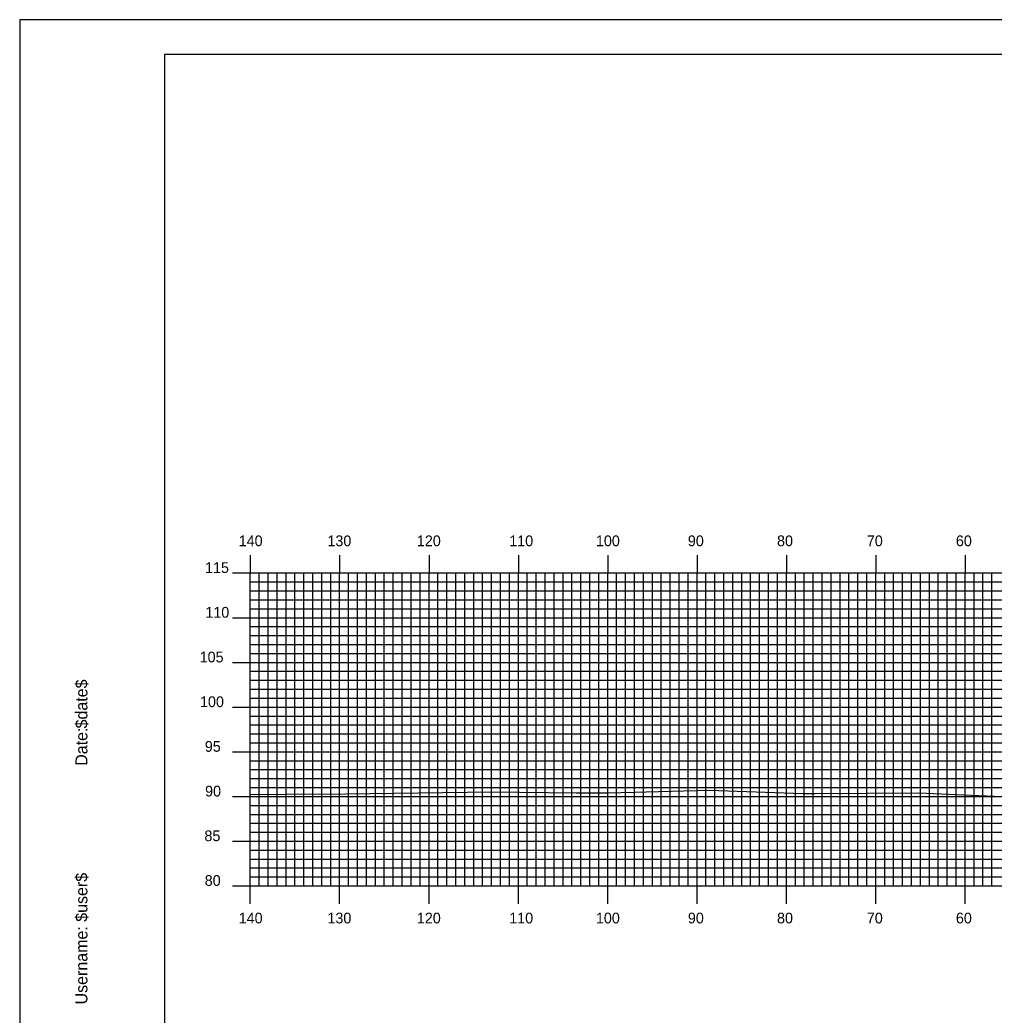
# Model space of a CAD drawing. Extents: x 1761397 to 1761741, y 442591 to 442811.
# Drawn here: x 1761397.5 to 1761506.5, y 442699.2 to 442810.5 of the extents above; entities that cross this region are included whole.
import ezdxf

# ---------------------------------------------------------------- set-up
doc = ezdxf.new("R2010")
doc.units = 0
for name, color, linetype in [('BORDER', 7, 'Continuous'), ('H_V ANNOTATION', 7, 'Continuous'), ('MAJOR', 7, 'Continuous'), ('MINOR', 7, 'Continuous'), ('PLOT BOUNDARY', 7, 'Continuous'), ('S_Roadway_Centerline', 7, 'Continuous')]:
    doc.layers.add(name, color=color, linetype=linetype)

msp = doc.modelspace()

# ---------------------------------------------------------------- linework, layer by layer
at = {"layer": 'BORDER'}
msp.add_lwpolyline([(1761413.64, 442596.67), (1761733.64, 442596.67), (1761733.64, 442806.67), (1761413.64, 442806.67)], close=True, dxfattribs=at)
at = {"layer": 'MAJOR'}
for p, q in [((1761423.24, 442750.67), (1761423.24, 442748.67)), ((1761433.24, 442750.67), (1761433.24, 442748.67)), ((1761443.24, 442750.67), (1761443.24, 442748.67)), ((1761453.24, 442750.67), (1761453.24, 442748.67)), ((1761463.24, 442750.67), (1761463.24, 442748.67)), ((1761473.24, 442750.67), (1761473.24, 442748.67)), ((1761483.24, 442750.67), (1761483.24, 442748.67)), ((1761493.24, 442750.67), (1761493.24, 442748.67)), ((1761503.24, 442750.67), (1761503.24, 442748.67)), ((1761421.24, 442748.67), (1761423.24, 442748.67)), ((1761423.24, 442748.67), (1761703.24, 442748.67)), ((1761423.24, 442713.67), (1761423.24, 442748.67)), ((1761423.24, 442713.67), (1761423.24, 442748.67)), ((1761423.24, 442748.67), (1761703.24, 442748.67)), ((1761433.24, 442713.67), (1761433.24, 442748.67)), ((1761443.24, 442713.67), (1761443.24, 442748.67)), ((1761453.24, 442713.67), (1761453.24, 442748.67)), ((1761463.24, 442713.67), (1761463.24, 442748.67)), ((1761473.24, 442713.67), (1761473.24, 442748.67)), ((1761483.24, 442713.67), (1761483.24, 442748.67)), ((1761493.24, 442713.67), (1761493.24, 442748.67)), ((1761503.24, 442713.67), (1761503.24, 442748.67)), ((1761421.24, 442743.67), (1761423.24, 442743.67)), ((1761423.24, 442743.67), (1761703.24, 442743.67)), ((1761421.24, 442738.67), (1761423.24, 442738.67)), ((1761423.24, 442738.67), (1761703.24, 442738.67)), ((1761421.24, 442733.67), (1761423.24, 442733.67)), ((1761423.24, 442733.67), (1761703.24, 442733.67)), ((1761421.24, 442728.67), (1761423.24, 442728.67)), ((1761423.24, 442728.67), (1761703.24, 442728.67)), ((1761421.24, 442723.67), (1761423.24, 442723.67)), ((1761423.24, 442723.67), (1761703.24, 442723.67)), ((1761421.24, 442718.67), (1761423.24, 442718.67)), ((1761423.24, 442718.67), (1761703.24, 442718.67)), ((1761421.24, 442713.67), (1761423.24, 442713.67)), ((1761423.24, 442713.67), (1761703.24, 442713.67)), ((1761423.24, 442713.67), (1761703.24, 442713.67)), ((1761423.24, 442711.66), (1761423.24, 442713.67)), ((1761433.24, 442711.66), (1761433.24, 442713.67)), ((1761443.24, 442711.66), (1761443.24, 442713.67)), ((1761453.24, 442711.66), (1761453.24, 442713.67)), ((1761463.24, 442711.66), (1761463.24, 442713.67)), ((1761473.24, 442711.66), (1761473.24, 442713.67)), ((1761483.24, 442711.66), (1761483.24, 442713.67)), ((1761493.24, 442711.66), (1761493.24, 442713.67)), ((1761503.24, 442711.66), (1761503.24, 442713.67))]:
    msp.add_line(p, q, dxfattribs=at)
at = {"layer": 'MINOR'}
for p, q in [((1761424.24, 442713.67), (1761424.24, 442748.67)), ((1761425.24, 442713.67), (1761425.24, 442748.67)), ((1761426.24, 442713.67), (1761426.24, 442748.67)), ((1761427.24, 442713.67), (1761427.24, 442748.67)), ((1761428.24, 442713.67), (1761428.24, 442748.67)), ((1761429.24, 442713.67), (1761429.24, 442748.67)), ((1761430.24, 442713.67), (1761430.24, 442748.67)), ((1761431.24, 442713.67), (1761431.24, 442748.67)), ((1761432.24, 442713.67), (1761432.24, 442748.67)), ((1761434.24, 442713.67), (1761434.24, 442748.67)), ((1761435.24, 442713.67), (1761435.24, 442748.67)), ((1761436.24, 442713.67), (1761436.24, 442748.67)), ((1761437.24, 442713.67), (1761437.24, 442748.67)), ((1761438.24, 442713.67), (1761438.24, 442748.67)), ((1761439.24, 442713.67), (1761439.24, 442748.67)), ((1761440.24, 442713.67), (1761440.24, 442748.67)), ((1761441.24, 442713.67), (1761441.24, 442748.67)), ((1761442.24, 442713.67), (1761442.24, 442748.67)), ((1761444.24, 442713.67), (1761444.24, 442748.67)), ((1761445.24, 442713.67), (1761445.24, 442748.67)), ((1761446.24, 442713.67), (1761446.24, 442748.67)), ((1761447.24, 442713.67), (1761447.24, 442748.67)), ((1761448.24, 442713.67), (1761448.24, 442748.67)), ((1761449.24, 442713.67), (1761449.24, 442748.67)), ((1761450.24, 442713.67), (1761450.24, 442748.67)), ((1761451.24, 442713.67), (1761451.24, 442748.67)), ((1761452.24, 442713.67), (1761452.24, 442748.67)), ((1761454.24, 442713.67), (1761454.24, 442748.67)), ((1761455.24, 442713.67), (1761455.24, 442748.67)), ((1761456.24, 442713.67), (1761456.24, 442748.67)), ((1761457.24, 442713.67), (1761457.24, 442748.67)), ((1761458.24, 442713.67), (1761458.24, 442748.67)), ((1761459.24, 442713.67), (1761459.24, 442748.67)), ((1761460.24, 442713.67), (1761460.24, 442748.67)), ((1761461.24, 442713.67), (1761461.24, 442748.67)), ((1761462.24, 442713.67), (1761462.24, 442748.67)), ((1761464.24, 442713.67), (1761464.24, 442748.67)), ((1761465.24, 442713.67), (1761465.24, 442748.67)), ((1761466.24, 442713.67), (1761466.24, 442748.67)), ((1761467.24, 442713.67), (1761467.24, 442748.67)), ((1761468.24, 442713.67), (1761468.24, 442748.67)), ((1761469.24, 442713.67), (1761469.24, 442748.67)), ((1761470.24, 442713.67), (1761470.24, 442748.67)), ((1761471.24, 442713.67), (1761471.24, 442748.67)), ((1761472.24, 442713.67), (1761472.24, 442748.67)), ((1761474.24, 442713.67), (1761474.24, 442748.67)), ((1761475.24, 442713.67), (1761475.24, 442748.67)), ((1761476.24, 442713.67), (1761476.24, 442748.67)), ((1761477.24, 442713.67), (1761477.24, 442748.67)), ((1761478.24, 442713.67), (1761478.24, 442748.67)), ((1761479.24, 442713.67), (1761479.24, 442748.67)), ((1761480.24, 442713.67), (1761480.24, 442748.67)), ((1761481.24, 442713.67), (1761481.24, 442748.67)), ((1761482.24, 442713.67), (1761482.24, 442748.67)), ((1761484.24, 442713.67), (1761484.24, 442748.67)), ((1761485.24, 442713.67), (1761485.24, 442748.67)), ((1761486.24, 442713.67), (1761486.24, 442748.67)), ((1761487.24, 442713.67), (1761487.24, 442748.67)), ((1761488.24, 442713.67), (1761488.24, 442748.67)), ((1761489.24, 442713.67), (1761489.24, 442748.67)), ((1761490.24, 442713.67), (1761490.24, 442748.67)), ((1761491.24, 442713.67), (1761491.24, 442748.67)), ((1761492.24, 442713.67), (1761492.24, 442748.67)), ((1761494.24, 442713.67), (1761494.24, 442748.67)), ((1761495.24, 442713.67), (1761495.24, 442748.67)), ((1761496.24, 442713.67), (1761496.24, 442748.67)), ((1761497.24, 442713.67), (1761497.24, 442748.67)), ((1761498.24, 442713.67), (1761498.24, 442748.67)), ((1761499.24, 442713.67), (1761499.24, 442748.67)), ((1761500.24, 442713.67), (1761500.24, 442748.67)), ((1761501.24, 442713.67), (1761501.24, 442748.67)), ((1761502.24, 442713.67), (1761502.24, 442748.67)), ((1761504.24, 442713.67), (1761504.24, 442748.67)), ((1761505.24, 442713.67), (1761505.24, 442748.67)), ((1761506.24, 442713.67), (1761506.24, 442748.67)), ((1761423.24, 442747.67), (1761703.24, 442747.67)), ((1761423.24, 442747.67), (1761425.24, 442747.67)), ((1761423.24, 442746.67), (1761703.24, 442746.67)), ((1761423.24, 442746.67), (1761425.24, 442746.67)), ((1761423.24, 442745.67), (1761703.24, 442745.67)), ((1761423.24, 442745.67), (1761425.24, 442745.67)), ((1761423.24, 442744.67), (1761703.24, 442744.67)), ((1761423.24, 442744.67), (1761425.24, 442744.67)), ((1761423.24, 442742.67), (1761703.24, 442742.67)), ((1761423.24, 442742.67), (1761425.24, 442742.67)), ((1761423.24, 442741.67), (1761703.24, 442741.67)), ((1761423.24, 442741.67), (1761425.24, 442741.67)), ((1761423.24, 442740.67), (1761703.24, 442740.67)), ((1761423.24, 442740.67), (1761425.24, 442740.67)), ((1761423.24, 442739.67), (1761703.24, 442739.67)), ((1761423.24, 442739.67), (1761425.24, 442739.67)), ((1761423.24, 442737.67), (1761703.24, 442737.67)), ((1761423.24, 442737.67), (1761425.24, 442737.67)), ((1761423.24, 442736.67), (1761703.24, 442736.67)), ((1761423.24, 442736.67), (1761425.24, 442736.67)), ((1761423.24, 442735.67), (1761703.24, 442735.67)), ((1761423.24, 442735.67), (1761425.24, 442735.67)), ((1761423.24, 442734.67), (1761703.24, 442734.67)), ((1761423.24, 442734.67), (1761425.24, 442734.67)), ((1761423.24, 442732.67), (1761703.24, 442732.67)), ((1761423.24, 442732.67), (1761425.24, 442732.67)), ((1761423.24, 442731.67), (1761703.24, 442731.67)), ((1761423.24, 442731.67), (1761425.24, 442731.67)), ((1761423.24, 442730.67), (1761703.24, 442730.67)), ((1761423.24, 442730.67), (1761425.24, 442730.67)), ((1761423.24, 442729.67), (1761703.24, 442729.67)), ((1761423.24, 442729.67), (1761425.24, 442729.67)), ((1761423.24, 442727.67), (1761703.24, 442727.67)), ((1761423.24, 442727.67), (1761425.24, 442727.67)), ((1761423.24, 442726.67), (1761703.24, 442726.67)), ((1761423.24, 442726.67), (1761425.24, 442726.67)), ((1761423.24, 442725.67), (1761703.24, 442725.67)), ((1761423.24, 442725.67), (1761425.24, 442725.67)), ((1761423.24, 442724.67), (1761703.24, 442724.67)), ((1761423.24, 442724.67), (1761425.24, 442724.67)), ((1761423.24, 442722.67), (1761703.24, 442722.67)), ((1761423.24, 442722.67), (1761425.24, 442722.67)), ((1761423.24, 442721.67), (1761703.24, 442721.67)), ((1761423.24, 442721.67), (1761425.24, 442721.67)), ((1761423.24, 442720.67), (1761703.24, 442720.67)), ((1761423.24, 442720.67), (1761425.24, 442720.67)), ((1761423.24, 442719.67), (1761703.24, 442719.67)), ((1761423.24, 442719.67), (1761425.24, 442719.67)), ((1761423.24, 442717.67), (1761703.24, 442717.67)), ((1761423.24, 442717.67), (1761425.24, 442717.67)), ((1761423.24, 442716.67), (1761703.24, 442716.67)), ((1761423.24, 442716.67), (1761425.24, 442716.67)), ((1761423.24, 442715.67), (1761703.24, 442715.67)), ((1761423.24, 442715.67), (1761425.24, 442715.67)), ((1761423.24, 442714.67), (1761703.24, 442714.67)), ((1761423.24, 442714.67), (1761425.24, 442714.67))]:
    msp.add_line(p, q, dxfattribs=at)
at = {"layer": 'PLOT BOUNDARY'}
msp.add_lwpolyline([(1761397.45, 442590.55), (1761737.45, 442590.55), (1761737.45, 442810.55), (1761397.45, 442810.55)], close=True, dxfattribs=at)
at = {"layer": 'S_Roadway_Centerline'}
msp.add_lwpolyline([(1761423.24, 442723.89), (1761427.17, 442723.94), (1761433.92, 442723.97), (1761442.06, 442724.06), (1761450.23, 442724.17), (1761459.7, 442724.06), (1761461.53, 442724.07), (1761463.34, 442724.09), (1761474.58, 442724.36), (1761485.07, 442724.01), (1761485.66, 442724.01), (1761486.46, 442724.01), (1761498.04, 442724.08), (1761507.32, 442723.65)], dxfattribs=at)

# ---------------------------------------------------------------- texts
at = {"layer": 'BORDER'}
for s, p in [('$date$', (1761405.01, 442731.28)), ('Date:', (1761405.01, 442727.1)), ('$user$', (1761405.01, 442709.65)), ('Username:', (1761405.01, 442700.4))]:
    msp.add_text(s, height=1.339, rotation=90, dxfattribs=at).set_placement(p)
at = {"layer": 'H_V ANNOTATION'}
for s, p in [('140', (1761421.94, 442751.67)), ('130', (1761431.87, 442751.67)), ('120', (1761441.88, 442751.67)), ('110', (1761452.22, 442751.67)), ('100', (1761461.92, 442751.67)), ('90', (1761472.21, 442751.67)), ('80', (1761482.19, 442751.67)), ('70', (1761492.24, 442751.67)), ('60', (1761502.21, 442751.67)), ('115', (1761418.17, 442748.67)), ('110', (1761418.21, 442743.67)), ('105', (1761417.57, 442738.67)), ('100', (1761417.61, 442733.67)), ('95', (1761418.15, 442728.67)), ('90', (1761418.18, 442723.67)), ('85', (1761418.11, 442718.67)), ('80', (1761418.14, 442713.67)), ('140', (1761421.94, 442709.47)), ('130', (1761431.87, 442709.47)), ('120', (1761441.88, 442709.47)), ('110', (1761452.22, 442709.47)), ('100', (1761461.92, 442709.47)), ('90', (1761472.21, 442709.47)), ('80', (1761482.19, 442709.47)), ('70', (1761492.24, 442709.47)), ('60', (1761502.21, 442709.47))]:
    msp.add_text(s, height=1.2, dxfattribs=at).set_placement(p)
at = {"layer": 'MAJOR'}
msp.add_text('-', height=0.012, dxfattribs=at).set_placement((1761423.23, 442713.67))

doc.saveas('drawing.dxf')
